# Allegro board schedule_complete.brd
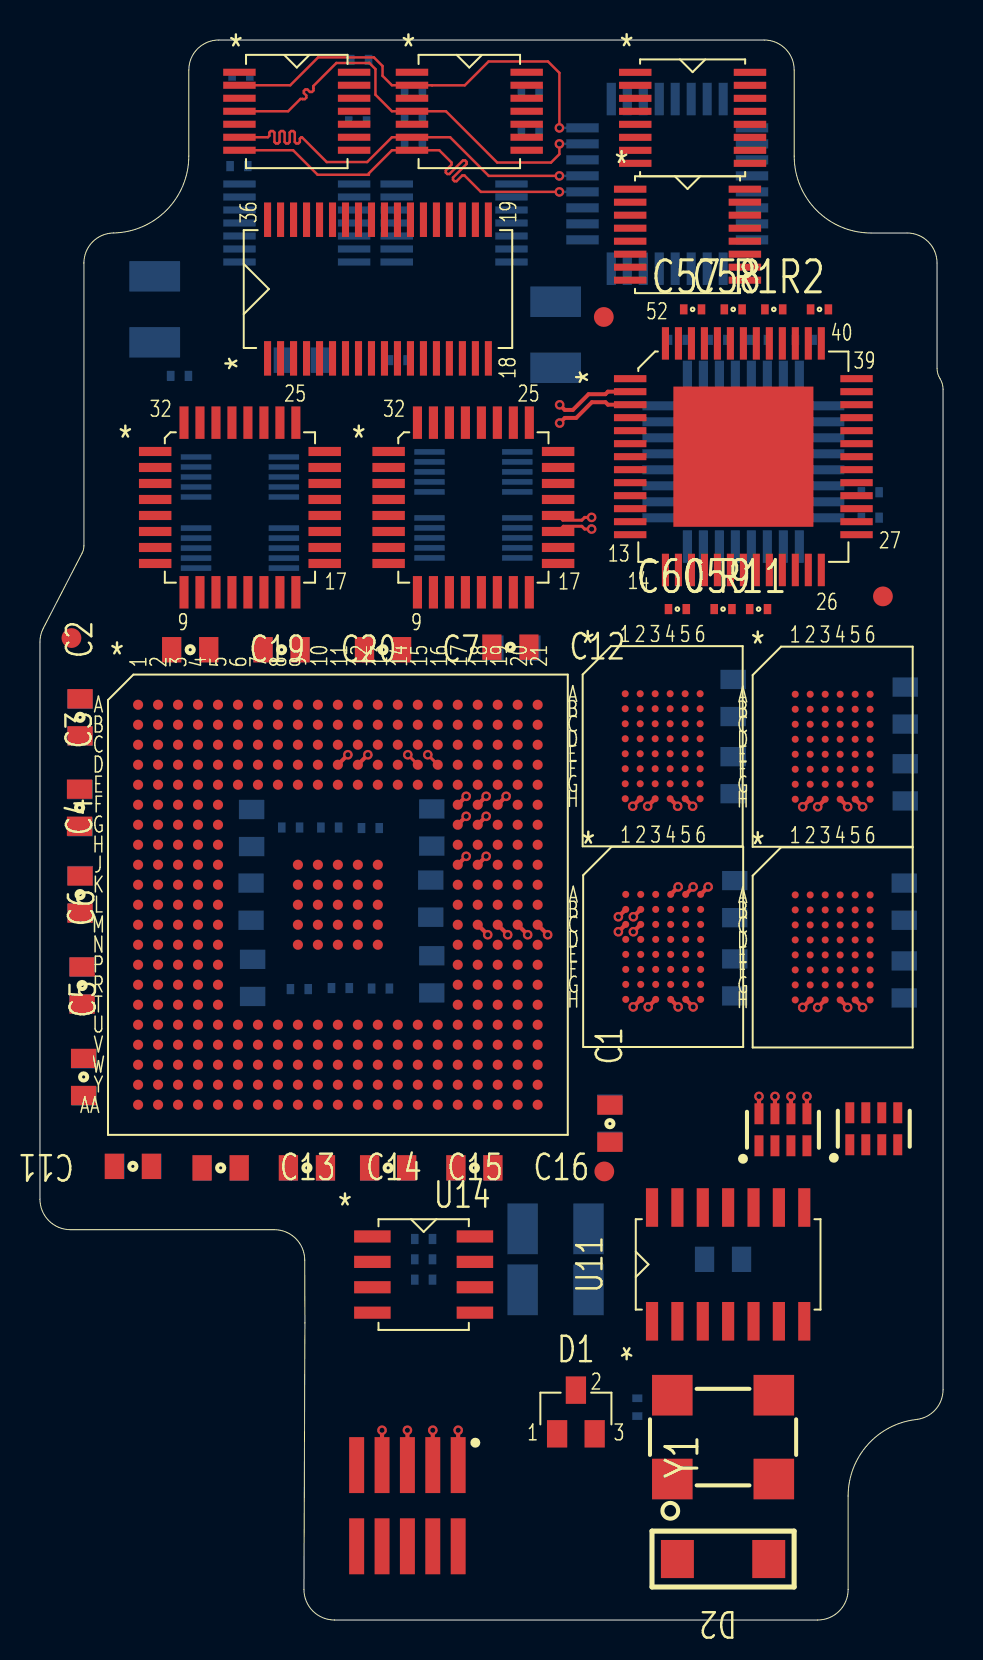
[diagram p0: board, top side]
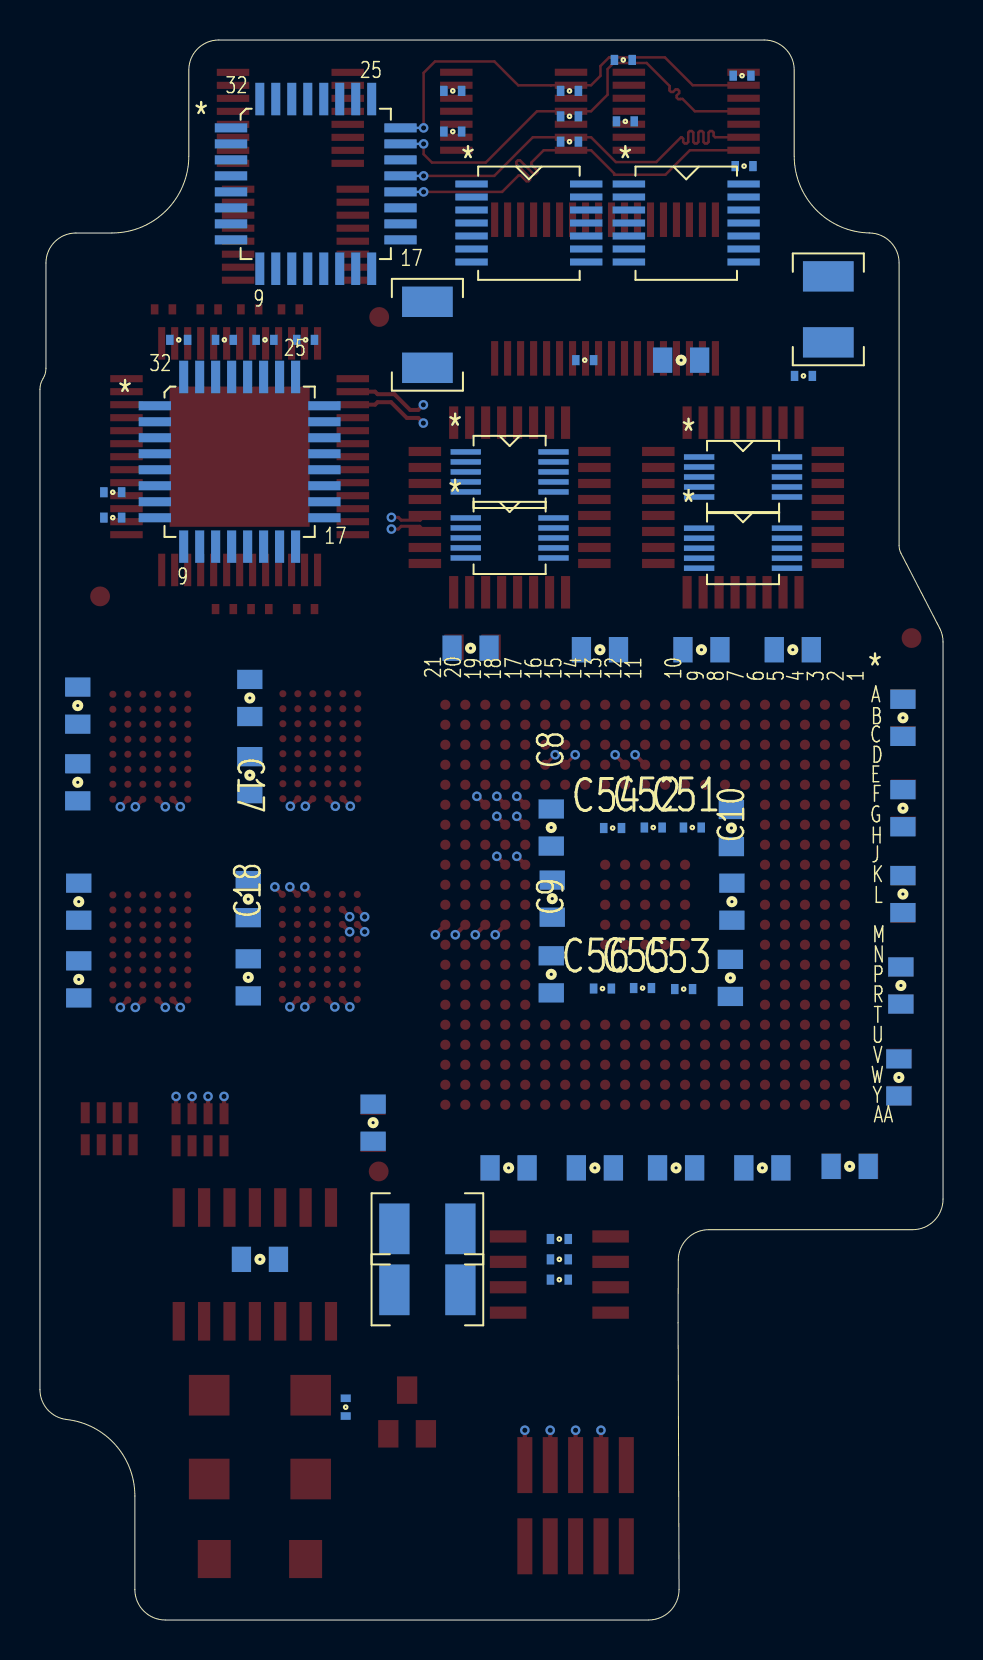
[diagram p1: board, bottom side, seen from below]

Outline 45.2 x 79 mm; copper layers: TOP, GND1, SIGNAL_1, PWR1, GND2, SIGNAL_2, PWR2, BOTTOM. Coordinates in mm from the lower left corner of the outline.
Outline path: 0,48.9 0,21.04 arc(0.45,19.96) 1.52,19.52 11.73,19.52 arc(12.8,19.07) 13.25,18 13.26,14.86 13.21,1.53 arc(13.66,0.45) 14.74,0 38.93,0 arc(40,0.45) 40.45,1.52 40.45,6.2 arc(41.43,8.77) 43.87,10.03 arc(44.82,10.52) 45.2,11.52 45.2,61.54 arc(45.16,61.81) 45.05,62.06 arc(44.94,62.32) 44.9,62.59 44.9,67.85 arc(44.46,68.91) 43.4,69.35 41.6,69.35 arc(38.88,70.48) 37.75,73.2 37.75,77.5 arc(37.31,78.56) 36.25,79 8.95,79 arc(7.89,78.56) 7.45,77.5 7.45,73.2 arc(6.35,70.5) 3.67,69.35 arc(2.63,68.9) 2.2,67.85 2.2,53.71 arc(2.18,53.52) 2.11,53.35 0.17,49.59 arc(0.04,49.26) 0,48.9

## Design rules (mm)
constraint set DEFAULT: min track width 0.127
net group CLOCK1: nets CLOCK1 CLOCK_OUT
net group DP: nets DP_N DP_P
net group PHASE: nets PHASE_N PHASE_P
net group BYTELANE0: nets DDR3_DM0 DDR3_DQ0 DDR3_DQ1 DDR3_DQ2 DDR3_DQ3 DDR3_DQS0_N DDR3_DQS0_P
net group LENGTH: nets LENGTH1 LENGTH2 LENGTH3 LENGTH4

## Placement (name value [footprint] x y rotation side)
C1  120PF  [SMC0805]  28.53 24.82 90 top
C2  120PF  [SMC0805]  2.01 45.14 90 top
C3  120PF  [SMC0805]  1.98 40.61 90 top
C4  120PF  [SMC0805]  2.01 36.27 90 top
C5  120PF  [SMC0805]  2.19 27.15 90 top
C6  120PF  [SMC0805]  2.11 31.72 90 top
C7  120PF  [SMC0805]  17.17 48.51 0 top
C8  120PF  [SMC0805]  19.61 39.62 90 bottom
C9  120PF  [SMC0805]  19.61 32.28 90 bottom
C10  120PF  [SMC0805]  10.57 35.92 90 bottom
C11  120PF  [SMC0805]  4.65 22.68 180 top
C12  120PF  [SMC0805]  23.55 48.64 0 top
C13  120PF  [SMC0805]  9.04 22.61 0 top
C14  120PF  [SMC0805]  13.36 22.61 0 top
C15  120PF  [SMC0805]  17.43 22.61 0 top
C16  120PF  [SMC0805]  21.74 22.61 0 top
C17  120PF  [SMC0805]  34.7 46.1 270 bottom
C18  120PF  [SMC0805]  34.77 32.13 90 bottom
C19  120PF  [SMC0805]  7.52 48.51 0 top
C20  120PF  [SMC0805]  12.09 48.51 0 top
C21  120PF  [SMC0805]  2.01 36.3 90 bottom
C22  120PF  [SMC0805]  2.11 31.72 90 bottom
C23  120PF  [SMC0805]  12.09 48.51 0 bottom
C24  120PF  [SMC0805]  2.21 27.13 90 bottom
C25  120PF  [SMC0805]  9.04 22.61 0 bottom
C26  120PF  [SMC0805]  17.17 48.51 0 bottom
C27  120PF  [SMC0805]  23.65 48.59 0 bottom
C28  120PF  [SMC0805]  19.56 36.07 90 bottom
C29  120PF  [SMC0805]  10.64 32.11 90 bottom
C30  120PF  [SMC0805]  10.59 39.6 90 bottom
C31  120PF  [SMC0805]  28.53 24.87 90 bottom
C32  120PF  [SMC0805]  7.52 48.51 0 bottom
C33  120PF  [SMC0805]  17.43 22.61 0 bottom
C34  120PF  [SMC0805]  13.36 22.61 0 bottom
C35  120PF  [SMC0805]  21.74 22.61 0 bottom
C36  120PF  [SMC0805]  4.68 22.68 180 bottom
C37  120PF  [SMC0805]  34.77 36.04 270 bottom
C38  120PF  [SMC0805]  34.7 42.24 270 bottom
C39  120PF  [SMC0805]  2.01 40.59 90 bottom
C40  120PF  [SMC0805]  2.01 45.11 90 bottom
C41  10uF  [1210RF]  5.74 65.53 270 bottom
C42  10uF  [1210RF]  25.81 64.26 270 bottom
C43  10uF  [1210RF]  25.81 16.51 180 bottom
C44  10uF  [1210RF]  25.81 19.56 180 bottom
C45  120PF  [SMC0805]  13.11 62.99 180 bottom
C46  120PF  [SMC0805]  43.26 32.03 90 bottom
C47  120PF  [SMC0805]  43.26 35.92 270 bottom
C48  120PF  [SMC0805]  43.31 45.72 270 bottom
C49  120PF  [SMC0805]  43.31 41.88 90 bottom
C50  120PF  [SMC0805]  34.19 18.03 180 bottom
C51  .1UF  [R_0402]  12.55 39.62 180 bottom
C52  .1UF  [R_0402]  14.5 39.62 180 bottom
C53  .1UF  [R_0402]  12.98 31.55 180 bottom
C54  .1UF  [R_0402]  16.54 39.6 180 bottom
C55  .1UF  [R_0402]  15.04 31.6 180 bottom
C56  .1UF  [R_0402]  17.04 31.57 180 bottom
C57  .1UF  [R_0402]  32.67 65.53 0 top
C58  .1UF  [R_0402]  34.7 65.53 0 top
C59  .1UF  [R_0402]  34.19 50.55 0 top
C60  .1UF  [R_0402]  31.9 50.55 0 top
D1  -  [SOT23_132]  26.82 10.41 0 top
D2  V  [SMF1806]  34.19 3.05 180 top
J1  FTSH-105-XX-X-DV  [SAMTEC_FTSH-105-XX-X-DV]  18.39 5.71 0 top
NOREF  -  [unnamed]  26.82 3.05 0 top
R1  10K  [R_0402]  36.73 65.53 0 top
R2  10K  [R_0402]  39.02 65.53 0 top
R3  10K  [R_0402]  31.9 64.01 180 bottom
R4  10K  [R_0402]  33.94 64.01 180 bottom
R5  10K  [R_0402]  35.97 64.01 180 bottom
R6  10K  [R_0402]  38.25 64.01 180 bottom
R7  10K  [R_0402]  17.93 62.99 180 bottom
R8  10K  [R_0402]  24.54 74.42 180 bottom
R9  10K  [R_0402]  16 78 180 bottom
R10  10K  [R_0402]  15.9 74.93 180 bottom
R11  10K  [R_0402]  35.97 50.55 0 top
R12  10K  [R_0402]  24.54 76.45 180 bottom
R13  10K  [R_0402]  18.7 76.45 180 bottom
R14  10K  [R_0402]  9.96 72.69 180 bottom
R15  10K  [R_0402]  10.06 77.22 180 bottom
R16  10K  [R_0402]  6.99 62.2 180 bottom
R17  10K  [R_0402]  18.7 75.18 180 bottom
R18  10K  [R_0402]  18.7 73.91 180 bottom
R19  10K  [R_0402]  41.56 56.39 180 bottom
R20  10K  [R_0402]  19.2 18.03 180 bottom
R21  10K  [R_0402]  19.2 19.05 180 bottom
R22  10K  [R_0402]  19.2 17.02 180 bottom
R23  10K  [R_0402]  41.56 55.12 180 bottom
R24  10K  [R_0402]  29.9 10.64 90 bottom
RN1  10K  [RESCAV80P160X320X70-8N]  37.19 24.51 90 top
RN2  10K  [RESCAV80P160X320X70-8N]  41.73 24.56 90 top
U1  -  [TSSOP14_26CC_BD4-4MM]  12.85 75.44 0 top
U2  -  [TSSOP14_26CC_BD4-4MM]  21.49 75.44 0 top
U3  -  [TSSOP14_26CC_BD4-4MM]  12.85 69.85 180 bottom
U4  -  [TSSOP14_26CC_BD4-4MM]  20.73 69.85 180 bottom
U5  -  [BGA345_BD23X23MM]  14.91 35.76 0 top
U7  -  [BGA48_BD7-5X9-5MM]  31.17 43.69 0 top
U8  -  [BGA48_BD7-5X9-5MM]  39.68 43.66 0 top
U9  -  [BGA48_BD7-5X9-5MM]  39.68 33.63 0 top
U10  -  [BGA48_BD7-5X9-5MM]  31.19 33.66 0 top
U11  -  [SO14NB]  34.44 17.78 90 top
U12  -  [TQFP52_BD10X10MM_THERM]  35.21 58.17 0 top
U13  -  [SSOP36_26CC_BD5-3MM]  16.92 66.55 90 top
U14  -  [SO8NB_V2]  19.2 17.27 0 top
U15  -  [TSSOP16_26CC_BD4-4MM]  32.41 69.27 0 top
U16  -  [TSSOP16_26CC_BD4-4MM]  32.67 75.11 0 top
U17  -  [TQFP32_32CC_BD7X7MM]  10.01 55.63 0 top
U18  -  [TQFP32_32CC_BD7X7MM]  21.69 55.63 0 top
U19  -  [TQFP32_32CC_BD7X7MM]  35.21 57.91 180 bottom
U20  -  [TQFP32_32CC_BD7X7MM]  31.4 71.81 180 bottom
U21  -  [MSOP10_20CC_BD3MM]  10.01 57.15 180 bottom
U22  -  [MSOP10_20CC_BD3MM]  10.01 53.59 180 bottom
U23  -  [MSOP10_20CC_BD3MM]  21.69 57.4 180 bottom
U24  -  [MSOP10_20CC_BD3MM]  21.69 54.1 180 bottom
Y1  -  [4CERAMIC]  34.19 9.14 90 top

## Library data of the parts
C1-C40 C45-C50 = CAP: Tolerance: 5%; alternate symbols: (VSMC0805L,VSMC0805R,VSMC0805B,SMC0805); part number: CAP_805-120PF,5%,50V,805; signal model: capacitor120pF; tolerance: 5%; signal model: DEFAULT_CAPACITOR_120.000000pF_2_1
C41-C44 = CAP: Tolerance: +80-20%; User Part Number: 110-1925-01; alternate symbols: (1210RF_WVI_10P;1210RF_V12P;1210WS;1210WS_WVI_10P); part number: CAP_SMT1210-110-1925-01,10UF,+80-20%,16V; tolerance: +80-20%; signal model: DEFAULT_CAPACITOR_1e+07pF_2_1
C51-C60 = CAP: alternate symbols: (VSMC0603L,VSMC0603R,VSMC0603B,SMC0603); part number: CAP_402-.1UF,&10%,80%,6.3V; signal model: capacitor0pF; tolerance: 10%; signal model: DEFAULT_CAPACITOR_100000pF_2_1
D1 = RCNET: User Part Number: 120-3831-01; Tolerance: 10%; part number: RCNET_SOT23-120-3831-01,CTXS03,50,46.4,50,150PF,10%; tolerance: 10%
D2 = BEAD_1806: Tolerance: T; User Part Number: P; part number: BEAD_1806_SMF1806-FBMH4516,TAIYO_FERRITE_BEAD,6A
J1 = SAMTEC_FTSH
R1-R24 = RES: alternate symbols: (VSMR0402B,VSMR0402R,VSMR0402L,0402); part number: RES_402-10K,1%,0402; signal model: resistor10K; tolerance: 1%; signal model: DEFAULT_RESISTOR_10000OHM_2_1
RN1 RN2 = RESNET_8: signal model: DEFAULT_RESISTOR_PACK_4_10000OHM
U1-U4 = LVC07: User Part Number: 100-7328-01; Tolerance: ***; part number: LVC07_TSSOP-100-7328-01,APW
U5 = TALON: User Part Number: 528-1123-01; Tolerance: ***; alternate symbols: (BGA345_BD23X23MM_NF); part number: TALON_BGA345-528-1123-01
U7-U10 = SRAM1MX16: User Part Number: 102-0026-01; Tolerance: ***; part number: SRAM1MX16_BGA-102-0026-01,55NS,K6F1616U6A-EF55
U11 = LVC00: User Part Number: 100-4554-01; Tolerance: ***; part number: LVC00_SO-100-4554-01
U12 = MC100ES6220: Tolerance: ***; User Part Number: 103-0009-01; alternate symbols: (TQFP52_BD10X10MM_THERM_NF); part number: MC100ES6220_TQFP-103-0009-01
U13 = LTC3731: User Part Number: 104-0019-01; Tolerance: ***; part number: LTC3731_SSOP36-104-0019-01
U14 = EEPROM8KX8: Tolerance: ***; User Part Number: 101-0054-01; part number: EEPROM8KX8_SO8-101-0054-01,M34D64
U15 U16 = PCA9554: User Part Number: 100-7579-01; Tolerance: ***; part number: PCA9554_TSSOP-100-7579-01
U17-U20 = CY2HH8110: Tolerance: ***; User Part Number: 100-7829-01; part number: CY2HH8110_TQFP-100-7829-01
U21-U24 = MAX1343: User Part Number: 104-0099-01; Tolerance: ***; part number: MAX1343_MSOP-104-0099-01,10BITADC
Y1 = OSC: part number: OSC_CERAMIC-66.00MHZ,CLOCKING,SG8002JF

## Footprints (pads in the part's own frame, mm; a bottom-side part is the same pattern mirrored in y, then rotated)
4CERAMIC
  rect 2.032x2.032 smd: 1(-2.095,2.54) 2(-2.095,-2.54) 3(2.095,-2.54) 4(2.095,2.54)
1210RF
  rect 1.524x2.54 smd: 1(-1.651,0) 2(1.651,0)
BGA48_BD7-5X9-5MM
  round 0.356 smd: A1(-1.875,2.625) A2(-1.125,2.625) A3(-0.375,2.625) A4(0.375,2.625) A5(1.125,2.625) A6(1.875,2.625) B1(-1.875,1.875) B2(-1.125,1.875) B3(-0.375,1.875) B4(0.375,1.875) B5(1.125,1.875) B6(1.875,1.875) C1(-1.875,1.125) C2(-1.125,1.125) C3(-0.375,1.125) C4(0.375,1.125) C5(1.125,1.125) C6(1.875,1.125) D1(-1.875,0.375) D2(-1.125,0.375) D3(-0.375,0.375) D4(0.375,0.375) D5(1.125,0.375) D6(1.875,0.375) E1(-1.875,-0.375) E2(-1.125,-0.375) E3(-0.375,-0.375) E4(0.375,-0.375) E5(1.125,-0.375) E6(1.875,-0.375) F1(-1.875,-1.125) F2(-1.125,-1.125) F3(-0.375,-1.125) F4(0.375,-1.125) F5(1.125,-1.125) F6(1.875,-1.125) G1(-1.875,-1.875) G2(-1.125,-1.875) G3(-0.375,-1.875) G4(0.375,-1.875) G5(1.125,-1.875) G6(1.875,-1.875) H1(-1.875,-2.625) H2(-1.125,-2.625) H3(-0.375,-2.625) H4(0.375,-2.625) H5(1.125,-2.625) H6(1.875,-2.625)
BGA345_BD23X23MM
  round 0.991 smd: (-13.335,13.335) (13.335,-13.335)
  round 0.508 smd: A1(-10,10) A2(-9,10) A3(-8,10) A4(-7,10) A5(-6,10) A6(-5,10) A7(-4,10) A8(-3,10) A9(-2,10) A10(-1,10) A11(0,10) A12(1,10) A13(2,10) A14(3,10) A15(4,10) A16(5,10) A17(6,10) A18(7,10) A19(8,10) A20(9,10) A21(10,10) AA1(-10,-10) AA2(-9,-10) AA3(-8,-10) AA4(-7,-10) AA5(-6,-10) AA6(-5,-10) AA7(-4,-10) AA8(-3,-10) AA9(-2,-10) AA10(-1,-10) AA11(0,-10) AA12(1,-10) AA13(2,-10) AA14(3,-10) AA15(4,-10) AA16(5,-10) AA17(6,-10) AA18(7,-10) AA19(8,-10) AA20(9,-10) AA21(10,-10) B1(-10,9) B2(-9,9) B3(-8,9) B4(-7,9) B5(-6,9) B6(-5,9) B7(-4,9) B8(-3,9) B9(-2,9) B10(-1,9) B11(0,9) B12(1,9) B13(2,9) B14(3,9) B15(4,9) B16(5,9) B17(6,9) B18(7,9) B19(8,9) B20(9,9) B21(10,9) C1(-10,8) C2(-9,8) C3(-8,8) C4(-7,8) C5(-6,8) C6(-5,8) C7(-4,8) C8(-3,8) C9(-2,8) C10(-1,8) C11(0,8) C12(1,8) C13(2,8) C14(3,8) C15(4,8) C16(5,8) C17(6,8) C18(7,8) C19(8,8) C20(9,8) C21(10,8) D1(-10,7) D2(-9,7) D3(-8,7) D4(-7,7) D5(-6,7) D6(-5,7) D7(-4,7) D8(-3,7) D9(-2,7) D10(-1,7) D11(0,7) D12(1,7) D13(2,7) D14(3,7) D15(4,7) D16(5,7) D17(6,7) D18(7,7) D19(8,7) D20(9,7) D21(10,7) E1(-10,6) E2(-9,6) E3(-8,6) E4(-7,6) E5(-6,6) E6(-5,6) E7(-4,6) E8(-3,6) E9(-2,6) E10(-1,6) E11(0,6) E12(1,6) E13(2,6) E14(3,6) E15(4,6) E16(5,6) E17(6,6) E18(7,6) E19(8,6) E20(9,6) E21(10,6) F1(-10,5) F2(-9,5) F3(-8,5) F4(-7,5) F5(-6,5) F17(6,5) F18(7,5) F19(8,5) F20(9,5) F21(10,5) G1(-10,4) G2(-9,4) G3(-8,4) G4(-7,4) G5(-6,4) G17(6,4) G18(7,4) G19(8,4) G20(9,4) G21(10,4) H1(-10,3) H2(-9,3) H3(-8,3) H4(-7,3) H5(-6,3) H17(6,3) H18(7,3) H19(8,3) H20(9,3) H21(10,3) J1(-10,2) J2(-9,2) J3(-8,2) J4(-7,2) J5(-6,2) J9(-2,2) J10(-1,2) J11(0,2) J12(1,2) J13(2,2) J17(6,2) J18(7,2) J19(8,2) J20(9,2) J21(10,2) K1(-10,1) K2(-9,1) K3(-8,1) K4(-7,1) K5(-6,1) K9(-2,1) K10(-1,1) K11(0,1) K12(1,1) K13(2,1) K17(6,1) K18(7,1) K19(8,1) K20(9,1) K21(10,1) L1(-10,0) L2(-9,0) L3(-8,0) L4(-7,0) L5(-6,0) L9(-2,0) L10(-1,0) L11(0,0) L12(1,0) L13(2,0) L17(6,0) L18(7,0) L19(8,0) L20(9,0) L21(10,0) M1(-10,-1) M2(-9,-1) M3(-8,-1) M4(-7,-1) M5(-6,-1) M9(-2,-1) M10(-1,-1) M11(0,-1) M12(1,-1) M13(2,-1) M17(6,-1) M18(7,-1) M19(8,-1) M20(9,-1) M21(10,-1) N1(-10,-2) N2(-9,-2) N3(-8,-2) N4(-7,-2) N5(-6,-2) N9(-2,-2) N10(-1,-2) N11(0,-2) N12(1,-2) N13(2,-2) N17(6,-2) N18(7,-2) N19(8,-2) N20(9,-2) N21(10,-2) P1(-10,-3) P2(-9,-3) P3(-8,-3) P4(-7,-3) P5(-6,-3) P17(6,-3) P18(7,-3) P19(8,-3) P20(9,-3) P21(10,-3) R1(-10,-4) R2(-9,-4) R3(-8,-4) R4(-7,-4) R5(-6,-4) R17(6,-4) R18(7,-4) R19(8,-4) R20(9,-4) R21(10,-4) T1(-10,-5) T2(-9,-5) T3(-8,-5) T4(-7,-5) T5(-6,-5) T17(6,-5) T18(7,-5) T19(8,-5) T20(9,-5) T21(10,-5) U1(-10,-6) U2(-9,-6) U3(-8,-6) U4(-7,-6) U5(-6,-6) U6(-5,-6) U7(-4,-6) U8(-3,-6) U9(-2,-6) U10(-1,-6) U11(0,-6) U12(1,-6) U13(2,-6) U14(3,-6) U15(4,-6) U16(5,-6) U17(6,-6) U18(7,-6) U19(8,-6) U20(9,-6) U21(10,-6) V1(-10,-7) V2(-9,-7) V3(-8,-7) V4(-7,-7) V5(-6,-7) V6(-5,-7) V7(-4,-7) V8(-3,-7) V9(-2,-7) V10(-1,-7) V11(0,-7) V12(1,-7) V13(2,-7) V14(3,-7) V15(4,-7) V16(5,-7) V17(6,-7) V18(7,-7) V19(8,-7) V20(9,-7) V21(10,-7) W1(-10,-8) W2(-9,-8) W3(-8,-8) W4(-7,-8) W5(-6,-8) W6(-5,-8) W7(-4,-8) W8(-3,-8) W9(-2,-8) W10(-1,-8) W11(0,-8) W12(1,-8) W13(2,-8) W14(3,-8) W15(4,-8) W16(5,-8) W17(6,-8) W18(7,-8) W19(8,-8) W20(9,-8) W21(10,-8) Y1(-10,-9) Y2(-9,-9) Y3(-8,-9) Y4(-7,-9) Y5(-6,-9) Y6(-5,-9) Y7(-4,-9) Y8(-3,-9) Y9(-2,-9) Y10(-1,-9) Y11(0,-9) Y12(1,-9) Y13(2,-9) Y14(3,-9) Y15(4,-9) Y16(5,-9) Y17(6,-9) Y18(7,-9) Y19(8,-9) Y20(9,-9) Y21(10,-9)
MSOP10_20CC_BD3MM
  rect 1.524x0.279 smd: 1(-2.197,1) 2(-2.197,0.5) 3(-2.197,0) 4(-2.197,-0.5) 5(-2.197,-1) 6(2.197,-1) 7(2.197,-0.5) 8(2.197,0) 9(2.197,0.5) 10(2.197,1)
R_0402
  rect 0.381x0.508 smd: 1(-0.445,0) 2(0.445,0)
RESCAV80P160X320X70-8N
  rect 1.05x0.45 smd: 1(-0.8,1.2) 2(-0.8,0.4) 3(-0.8,-0.4) 4(-0.8,-1.2) 5(0.8,-1.2) 6(0.8,-0.4) 7(0.8,0.4) 8(0.8,1.2)
SAMTEC_FTSH-105-XX-X-DV
  rect 0.75x2.8 smd: 1(2.54,2.03) 2(2.54,-2.03) 3(1.27,2.03) 4(1.27,-2.03) 5(0,2.03) 6(0,-2.03) 7(-1.27,2.03) 8(-1.27,-2.03) 9(-2.54,2.03) 10(-2.54,-2.03)
SMC0805
  rect 0.965x1.27 smd: 1(-0.927,0) 2(0.927,0)
SMF1806
  rect 1.651x1.905 smd: 1(-2.286,0) 2(2.286,0)
SO8NB_V2
  rect 1.829x0.61 smd: 1(-2.565,1.905) 2(-2.565,0.635) 3(-2.565,-0.635) 4(-2.565,-1.905) 5(2.565,-1.905) 6(2.565,-0.635) 7(2.565,0.635) 8(2.565,1.905)
SO14NB
  rect 1.93x0.61 smd: 1(-2.845,3.81) 2(-2.845,2.54) 3(-2.845,1.27) 4(-2.845,0) 5(-2.845,-1.27) 6(-2.845,-2.54) 7(-2.845,-3.81) 8(2.845,-3.81) 9(2.845,-2.54) 10(2.845,-1.27) 11(2.845,0) 12(2.845,1.27) 13(2.845,2.54) 14(2.845,3.81)
SOT23_132
  rect 1.016x1.372 smd: 1(-0.94,-1.105) 2(0,1.079) 3(0.94,-1.105)
SSOP36_26CC_BD5-3MM
  rect 1.727x0.356 smd: 1(-3.467,5.525) 2(-3.467,4.875) 3(-3.467,4.225) 4(-3.467,3.575) 5(-3.467,2.925) 6(-3.467,2.275) 7(-3.467,1.625) 8(-3.467,0.975) 9(-3.467,0.325) 10(-3.467,-0.325) 11(-3.467,-0.975) 12(-3.467,-1.625) 13(-3.467,-2.275) 14(-3.467,-2.925) 15(-3.467,-3.575) 16(-3.467,-4.225) 17(-3.467,-4.875) 18(-3.467,-5.525) 19(3.467,-5.525) 20(3.467,-4.875) 21(3.467,-4.225) 22(3.467,-3.575) 23(3.467,-2.925) 24(3.467,-2.275) 25(3.467,-1.625) 26(3.467,-0.975) 27(3.467,-0.325) 28(3.467,0.325) 29(3.467,0.975) 30(3.467,1.625) 31(3.467,2.275) 32(3.467,2.925) 33(3.467,3.575) 34(3.467,4.225) 35(3.467,4.875) 36(3.467,5.525)
TQFP32_32CC_BD7X7MM
  rect 1.626x0.457 smd: 1(-4.242,2.8) 2(-4.242,2) 3(-4.242,1.2) 4(-4.242,0.4) 5(-4.242,-0.4) 6(-4.242,-1.2) 7(-4.242,-2) 8(-4.242,-2.8) 17(4.242,-2.8) 18(4.242,-2) 19(4.242,-1.2) 20(4.242,-0.4) 21(4.242,0.4) 22(4.242,1.2) 23(4.242,2) 24(4.242,2.8)
  rect 0.457x1.626 smd: 9(-2.8,-4.242) 10(-2,-4.242) 11(-1.2,-4.242) 12(-0.4,-4.242) 13(0.4,-4.242) 14(1.2,-4.242) 15(2,-4.242) 16(2.8,-4.242) 25(2.8,4.242) 26(2,4.242) 27(1.2,4.242) 28(0.4,4.242) 29(-0.4,4.242) 30(-1.2,4.242) 31(-2,4.242) 32(-2.8,4.242)
TQFP52_BD10X10MM_THERM
  round 0.991 smd: (-6.985,6.985) (6.985,-6.985)
  rect 1.626x0.356 smd: 1(-5.664,3.9) 2(-5.664,3.25) 3(-5.664,2.6) 4(-5.664,1.95) 5(-5.664,1.3) 6(-5.664,0.65) 7(-5.664,0) 8(-5.664,-0.65) 9(-5.664,-1.3) 10(-5.664,-1.95) 11(-5.664,-2.6) 12(-5.664,-3.25) 13(-5.664,-3.9) 27(5.664,-3.9) 28(5.664,-3.25) 29(5.664,-2.6) 30(5.664,-1.95) 31(5.664,-1.3) 32(5.664,-0.65) 33(5.664,0) 34(5.664,0.65) 35(5.664,1.3) 36(5.664,1.95) 37(5.664,2.6) 38(5.664,3.25) 39(5.664,3.9)
  rect 0.356x1.626 smd: 14(-3.9,-5.664) 15(-3.25,-5.664) 16(-2.6,-5.664) 17(-1.95,-5.664) 18(-1.3,-5.664) 19(-0.65,-5.664) 20(0,-5.664) 21(0.65,-5.664) 22(1.3,-5.664) 23(1.95,-5.664) 24(2.6,-5.664) 25(3.25,-5.664) 26(3.9,-5.664) 40(3.9,5.664) 41(3.25,5.664) 42(2.6,5.664) 43(1.95,5.664) 44(1.3,5.664) 45(0.65,5.664) 46(0,5.664) 47(-0.65,5.664) 48(-1.3,5.664) 49(-1.95,5.664) 50(-2.6,5.664) 51(-3.25,5.664) 52(-3.9,5.664)
TSSOP14_26CC_BD4-4MM
  rect 1.626x0.356 smd: 1(-2.87,1.95) 2(-2.87,1.3) 3(-2.87,0.65) 4(-2.87,0) 5(-2.87,-0.65) 6(-2.87,-1.3) 7(-2.87,-1.95) 8(2.87,-1.95) 9(2.87,-1.3) 10(2.87,-0.65) 11(2.87,0) 12(2.87,0.65) 13(2.87,1.3) 14(2.87,1.95)
TSSOP16_26CC_BD4-4MM
  rect 1.626x0.356 smd: 1(-2.87,2.275) 2(-2.87,1.625) 3(-2.87,0.975) 4(-2.87,0.325) 5(-2.87,-0.325) 6(-2.87,-0.975) 7(-2.87,-1.625) 8(-2.87,-2.275) 9(2.87,-2.275) 10(2.87,-1.625) 11(2.87,-0.975) 12(2.87,-0.325) 13(2.87,0.325) 14(2.87,0.975) 15(2.87,1.625) 16(2.87,2.275)
unnamed
  round 0 hole 3.175 unplated: (0,0)

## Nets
GND: C1.2(B<0>) C2.2(B<0>) C3.2(B<0>) C4.2(B<0>) C5.2(B<0>) C6.2(B<0>) C7.2(B<0>) C8.2(B<0>) C9.2(B<0>) C10.2(B<0>) C11.2(B<0>) C12.2(B<0>) C13.2(B<0>) C14.2(B<0>) C15.2(B<0>) C16.2(B<0>) C17.2(B<0>) C18.2(B<0>) C19.2(B<0>) C20.2(B<0>) C21.2(B<0>) C22.2(B<0>) C23.2(B<0>) C24.2(B<0>) C25.2(B<0>) C26.2(B<0>) C27.2(B<0>) C28.2(B<0>) C29.2(B<0>) C30.2(B<0>) C31.2(B<0>) C32.2(B<0>) C33.2(B<0>) C34.2(B<0>) C35.2(B<0>) C36.2(B<0>) C37.2(B<0>) C38.2(B<0>) C39.2(B<0>) C40.2(B<0>) C41.2(B<0>) C42.2(B<0>) C43.1 C44.1 C45.2(B<0>) C46.2(B<0>) C47.2(B<0>) C48.2(B<0>) C49.2(B<0>) C50.2(B<0>) C51.2(B<0>) C52.2(B<0>) C53.2(B<0>) C54.2(B<0>) C55.2(B<0>) C56.2(B<0>) C57.2(B<0>) C58.2(B<0>) C59.2(B<0>) C60.2(B<0>) U2.1 U3.1 U4.1 U7.D3 U7.D4 U7.F3 U7.F4 U8.D3 U8.D4 U8.F3 U8.F4 U9.D3 U9.D4 U9.F3 U9.F4 U10.D3 U10.D4 U10.F3 U10.F4 U11.7 U12.7 U12.13 U12.20 U12.26 U12.29 U12.36 U12.45 U12.52 U13.7 U13.15 U13.22 U13.34 U14.1 U14.7(WC_N) U15.1 U16.1 U17.4 U17.13 U17.21 U17.28 U18.4 U18.13 U18.21 U18.29(VDD<8>) U19.3 U19.14 U19.18 U19.22 U19.28 U20.4 U20.13 U20.18 U20.29(VDD<8>) U21.1 U22.1 U23.1 U24.1
VCC: C1.1 C2.1 C3.1 C4.1 C5.1 C6.1 C7.1 C8.1 C9.1 C10.1 C11.1 C12.1 C13.1 C14.1 C15.1 C16.1 C17.1 C18.1 C19.1 C20.1 C21.1 C22.1 C23.1 C24.1 C25.1 C26.1 C27.1 C28.1 C29.1 C30.1 C31.1 C32.1 C33.1 C34.1 C35.1 C36.1 C37.1 C38.1 C39.1 C40.1 C41.1 C42.1 C43.2(B<0>) C44.2(B<0>) C45.1 C46.1 C47.1 C48.1 C49.1 C50.1 C51.1 C52.1 C53.1 C54.1 C55.1 C56.1 C57.1 C58.1 C59.1 C60.1 D2.1 R22.2(B<0>) R23.2(B<0>) RN1.1 RN1.2 RN1.3 RN1.4 RN2.1 RN2.2 RN2.3 RN2.4 U1.5 U1.8 U2.5 U2.8 U3.8 U4.8 U7.C3 U7.C4 U7.E3 U7.E4 U8.C3 U8.C4 U8.E3 U8.E4 U9.C3 U9.C4 U9.E3 U9.E4 U10.C3 U10.C4 U10.E3 U10.E4 U11.14 U12.6 U12.12 U12.19 U12.25 U12.28 U12.37 U13.5 U13.18 U13.27 U13.36 U15.9 U15.14 U16.9 U16.13 U17.5 U17.19 U17.27 U18.14 U18.27 U20.5 U20.12 U20.19 U20.30 U21.9 U21.10(VDD) U22.9 U22.10(VDD) U23.9 U23.10(VDD) U24.9 U24.10(VDD) Y1.2 Y1.4(VCC)
1: U5.A1 U17.9
2: U5.A2 U17.10
3: U5.B2 U17.12
4: U5.B3 U17.14
5: U5.B4 U17.15
6: U5.C4 U17.16 U18.10
A6: U12.21
ANY_LAYER_NET: U3.13 U4.13 U13.35 U15.4
CLK_OUT: Y1.3
CLOCK1: R24.1 Y1.1
CLOCK_OUT: R24.2(B<0>) U11.1 U14.6
DDR3_A0: J1.1(TP-1) RN1.8 U5.M21 U7.H2 U8.H2 U9.H2 U10.H2
DDR3_A1: J1.3 RN1.7 U5.M20 U7.H3 U8.H3 U9.H3 U10.H3
DDR3_A2: J1.5 RN1.6 U5.M19 U7.H4 U8.H4 U9.H4 U10.H4
DDR3_A3: J1.7 RN1.5(B) U5.M18 U7.H5 U8.H5 U9.H5 U10.H5
DDR3_A4: J1.9 RN2.5(B) U5.M17 U7.F6 U8.F6 U9.F6 U10.F6
DDR3_A5: J1.10 RN2.6 U5.N21 U7.G6 U8.G6 U9.G6 U10.G6
DDR3_A6: J1.8 RN2.7 U5.P17 U7.G5(WE_N) U8.G5(WE_N) U9.G5(WE_N) U10.G5(WE_N)
DDR3_A7: J1.6 RN2.8 U5.N19 U7.G4 U8.G4 U9.G4 U10.G4
DDR3_DM0: U5.F19 U10.A4
DDR3_DQ0: U5.J17 U10.C2
DDR3_DQ1: U5.F18 U10.A5
DDR3_DQ2: U5.J18 U10.C1
DDR3_DQ3: U5.F17 U10.A6
DDR3_DQS0_N: U5.G17 U10.B1
DDR3_DQS0_P: U5.G18 U10.B2
DP_N: U5.D15 U18.19
DP_P: U5.D16 U18.20
HDI_STACK: U3.9 U4.2(Y<1>) U13.32 U15.3 U20.6
LENGTH1: U1.2(Y<1>) U2.2(Y<1>) U20.24
LENGTH2: U1.4 U2.4 U20.23
LENGTH3: U1.6 U2.6 U20.21
LENGTH4: U1.7 U2.7 U20.20
NET1: U1.9
NET2: U1.10 U4.12
NET3: U1.11 U4.11
NET4: U12.9(VEE2) U17.6 U18.6
NET5: D1.2 D2.2(B) U11.2 U14.2
NET7: D1.1 U14.3
NET8: R16.2(B<0>) U2.9 U12.11 U15.2 U17.30 U18.9 U19.27 U20.22
NET9: U12.8 U15.10 U17.2 U18.1
NET11: U2.13 U16.15
NET12: R14.2(B<0>) U3.12 U4.3 U4.9 U20.2
NET13: U12.34 U17.23 U18.23
NET14: U19.8 U21.4 U22.6 U23.4
NET15: U19.17 U22.8 U24.7
NET17: U13.9 U17.11
NET20: U13.10 U17.32
NET24: U3.7 U11.3(Y_N<0>) U11.4 U16.14 U17.18 U20.17
NET25: U3.2(Y<1>) U11.11 U17.29(VDD<8>)
NET28: U11.6 U14.5 U18.31
NET31: R13.1 U1.3 U1.14 U2.3
NET33: R11.2(B<0>) U14.4 U19.12
NET34: U16.10
PECL1_N: U3.11 U11.10 U17.3
PECL1_P: U1.12 U3.10 U11.9 U17.26
PECL2_N: U11.13 U17.17
PECL2_P: U11.12 U18.16 U20.15
PHASE_N: U5.D12 U12.3
PHASE_P: U5.D11 U12.2

Pads without a net: D1 3; J1 2 4; R1 1 2; R2 1 2; R3 1 2; R4 1 2; R5 1 2; R6 1 2; R7 1 2; R8 1 2; R9 1 2; R10 1 2; R11 1; R12 1 2; R13 2; R14 1; R15 1 2; R16 1; R17 1 2; R18 1 2; R19 1 2; R20 1 2; R21 1 2; R22 1; R23 1; U1 1 13; U2 10 11 12 14; U3 3 4 5 6 14; U4 4 5 6 7 10 14; U5 A3 A4 A5 A6 A7 A8 A9 A10 A11 A12 A13 A14 A15 A16 A17 A18 A19 A20 A21 AA1 AA2 AA3 AA4 AA5 AA6 AA7 AA8 AA9 AA10 AA11 AA12 AA13 AA14 AA15 AA16 AA17 AA18 AA19 AA20 AA21 B1 B5 B6 B7 B8 B9 B10 B11 B12 B13 B14 B15 B16 B17 B18 B19 B20 B21 C1 C2 C3 C5 C6 C7 C8 C9 C10 C11 C12 C13 C14 C15 C16 C17 C18 C19 C20 C21 D1 D2 D3 D4 D5 D6 D7 D8 D9 D10 D13 D14 D17 D18 D19 D20 D21 E1 E2 E3 E4 E5 E6 E7 E8 E9 E10 E11 E12 E13 E14 E15 E16 E17 E18 E19 E20 E21 F1 F2 F3 F4 F5 F20 F21 G1 G2 G3 G4 G5 G19 G20 G21 H1 H2 H3 H4 H5 H17 H18 H19 H20 H21 J1 J2 J3 J4 J5 J9 J10 J11 J12 J13 J19 J20 J21 K1 K2 K3 K4 K5 K9 K10 K11 K12 K13 K17 K18 K19 K20 K21 L1 L2 L3 L4 L5 L9 L10 L11 L12 L13 L17 L18 L19 L20 L21 M1 M2 M3 M4 M5 M9 M10 M11 M12 M13 N1 N2 N3 N4 N5 N9 N10 N11 N12 N13 N17 N18 N20 P1 P2 P3 P4 P5 P18 P19 P20 P21 R1 R2 R3 R4 R5 R17 R18 R19 R20 R21 T1 T2 T3 T4 T5 T17 T18 T19 T20 T21 U1 U2 U3 U4 U5 U6 U7 U8 U9 U10 U11 U12 U13 U14 U15 U16 U17 U18 U19 U20 U21 V1 V2 V3 V4 V5 V6 V7 V8 V9 V10 V11 V12 V13 V14 V15 V16 V17 V18 V19 V20 V21 W1 W2 W3 W4 W5 W6 W7 W8 W9 W10 W11 W12 W13 W14 W15 W16 W17 W18 W19 W20 W21 Y1 Y2 Y3 Y4 Y5 Y6 Y7 Y8 Y9 Y10 Y11 Y12 Y13 Y14 Y15 Y16 Y17 Y18 Y19 Y20 Y21; U7 A1 A2 A3 A4 A5 A6 B1 B2 B3 B4 B5 B6 C1 C2 C5 C6 D1 D2 D5 D6 E1 E2 E5 E6 F1 F2 F5 G1 G2 G3 H1 H6; U8 A1 A2 A3 A4 A5 A6 B1 B2 B3 B4 B5 B6 C1 C2 C5 C6 D1 D2 D5 D6 E1 E2 E5 E6 F1 F2 F5 G1 G2 G3 H1 H6; U9 A1 A2 A3 A4 A5 A6 B1 B2 B3 B4 B5 B6 C1 C2 C5 C6 D1 D2 D5 D6 E1 E2 E5 E6 F1 F2 F5 G1 G2 G3 H1 H6; U10 A1 A2 A3 B3 B4 B5 B6 C5 C6 D1 D2 D5 D6 E1 E2 E5 E6 F1 F2 F5 G1 G2 G3 H1 H6; U11 5 8; U12 1 4 5 10 14 15 16 17 18 22 23 24 27 30 31 32 33 35 38 39 40 41 42 43 44 46 47 48 49 50 51; U13 1 2 3 4 6 8 11 12 13 14 16 17 19 20 21 23 24 25 26 28 29 30 31 33; U14 8; U15 5 6 7 8 11 12 13 15 16; U16 2 3 4 5 6 7 8 11 12 16; U17 1 7 8 20 22 24 25 31; U18 2 3 5 7 8 11 12 15 17 18 22 24 25 26 28 30 32; U19 1 2 4 5 6 7 9 10 11 13 15 16 19 20 21 23 24 25 26 29 30 31 32; U20 1 3 7 8 9 10 11 14 16 25 26 27 28 31 32; U21 2 3 5 6 7 8; U22 2 3 4 5 7; U23 2 3 5 6 7 8; U24 2 3 4 5 6 8

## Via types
v1: diameter 0.483, hole 0.254, TOP to BOTTOM, 54 vias

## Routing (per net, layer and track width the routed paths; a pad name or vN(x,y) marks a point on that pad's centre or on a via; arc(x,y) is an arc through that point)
DDR3_A0: length 94.7
  TOP w0.209: U10.H2 v1(29.69,30.66) ; U5.M21 v1(25.41,34.26) ; RN1.8 v1(35.99,26.18) ; U8.H2 v1(38.18,40.66) ; U9.H2 v1(38.18,30.63) ; J1.1 v1(20.93,9.49) ; U7.H2 v1(29.67,40.69)
  SIGNAL_1 w0.146: v1(20.93,9.49) 25.41,13.97 v1(25.41,34.26) 23.4,36.27 21.01,36.27 19.97,37.31 19.97,41.1 20.85,41.99 28.37,41.99 v1(29.67,40.69) 30.66,39.7 35.05,39.7 36.02,40.66 v1(38.18,40.66) 38.18,37.41 37.67,37.41 37.67,37.13 38.68,37.13 38.68,36.86 37.67,36.86 37.67,36.59 38.68,36.59 38.68,36.31 38.18,36.31 v1(38.18,30.63) 35.08,30.63 34.15,31.57 30.6,31.57 v1(29.69,30.66)
  SIGNAL_2 w0.146: v1(35.99,26.18) 35.29,26.87 32.18,26.87 29.69,29.36 v1(29.69,30.66)
DDR3_A1: length 94.8
  TOP w0.209: U7.H3 v1(30.42,40.69) ; U9.H3 v1(38.93,30.63) ; RN1.7 v1(36.79,26.18) ; J1.3 v1(19.66,9.49) ; U8.H3 v1(38.93,40.66) ; U5.M20 v1(24.41,34.26) ; U10.H3 v1(30.44,30.66)
  SIGNAL_1 w0.146: v1(19.66,9.49) 24.41,14.24 v1(24.41,34.26) 22.91,35.76 20.98,35.76 19.69,37.06 19.69,41.33 20.63,42.27 28.84,42.27 v1(30.42,40.69) 31.16,39.95 34.87,39.95 36,41.08 38.51,41.08 v1(38.93,40.66) 38.93,34.39 39.43,34.39 39.43,34.11 38.42,34.11 38.42,33.84 39.43,33.84 39.43,33.57 38.93,33.57 v1(38.93,30.63) 38.51,30.21 35.02,30.21 33.91,31.32 31.11,31.32 v1(30.44,30.66)
  SIGNAL_2 w0.146: v1(36.79,26.18) 35.56,27.41 32.72,27.41 30.44,29.68 v1(30.44,30.66)
DDR3_A2: length 94.4
  TOP w0.209: RN1.6 v1(37.59,26.18) ; U10.H4 v1(31.94,30.66) ; U9.H4 v1(40.43,30.63) ; U5.M19 v1(23.41,34.26) ; U8.H4 v1(40.43,40.66) ; U7.H4 v1(31.92,40.69) ; J1.5 v1(18.39,9.49)
  SIGNAL_1 w0.146: v1(18.39,9.49) 23.41,14.51 v1(23.41,34.26) 22.47,35.2 22.04,35.2 22.04,35.52 21.76,35.52 21.76,34.89 21.49,34.89 21.49,35.2 20.96,35.2 19.36,36.8 19.36,41.53 20.42,42.6 30.01,42.6 v1(31.92,40.69) 32.37,40.23 34.77,40.23 35.87,41.33 39.76,41.33 v1(40.43,40.66) v1(40.43,30.63) 39.69,29.9 34.93,29.9 33.75,31.07 32.36,31.07 v1(31.94,30.66)
  SIGNAL_2 w0.146: v1(31.94,30.66) 31.94,29.25 33.17,28.02 35.75,28.02 v1(37.59,26.18)
DDR3_A3: length 94
  TOP w0.209: U5.M18 v1(22.41,34.26) ; U10.H5 v1(32.69,30.66) ; U7.H5 v1(32.67,40.69) ; J1.7 v1(17.12,9.49) ; RN1.5 v1(38.39,26.18) ; U8.H5 v1(41.18,40.66) ; U9.H5 v1(41.18,30.63)
  SIGNAL_1 w0.146: v1(32.69,30.66) 33.73,29.62 40.16,29.62 v1(41.18,30.63) v1(41.18,40.66) 40.21,41.63 35.74,41.63 34.8,40.69 v1(32.67,40.69) 30.45,42.9 20.17,42.9 19.03,41.76 19.03,36.14 20.91,34.26 v1(22.41,34.26) 22.41,14.78 v1(17.12,9.49)
  SIGNAL_2 w0.146: v1(32.69,30.66) 32.69,29.64 33.78,28.55 36.02,28.55 v1(38.39,26.18)
DDR3_DM0: length 15.2
  TOP w0.209: U10.A4 v1(31.94,36.66) ; U5.F19 v1(23.33,41.19)
  SIGNAL_2 w0.127: v1(31.94,36.66) 30.02,38.58 29.81,38.36 29.63,38.54 30.05,38.97 29.87,39.15 29.45,38.72 29.27,38.9 29.69,39.33 29.51,39.51 29.09,39.08 28.91,39.26 29.33,39.69 29.16,39.87 28.94,39.66 27.41,41.19 v1(23.33,41.19)
DDR3_DQ0: length 15.8
  TOP w0.209: U10.C2 v1(29.7,34.41) ; U5.J17 v1(21.33,38.19)
  SIGNAL_2 w0.127: v1(21.33,38.19) 21.93,37.59 25,37.59 25.87,36.72 25.65,36.49 25.83,36.31 26.28,36.76 26.46,36.58 26,36.13 26.18,35.95 26.64,36.4 26.81,36.22 26.36,35.77 26.54,35.59 26.99,36.04 27.17,35.86 26.72,35.41 26.9,35.23 27.13,35.46 28.58,34.01 29.29,34.01 v1(29.7,34.41)
DDR3_DQ1: length 15.5
  TOP w0.209: U10.A5 v1(32.69,36.66) ; U5.F18 v1(22.33,41.19)
  SIGNAL_2 w0.127: v1(22.33,41.19) 22.75,41.61 27.74,41.61 31,38.35 31.21,38.56 31.39,38.39 30.96,37.96 31.14,37.78 31.57,38.21 31.75,38.03 31.53,37.81 v1(32.69,36.66)
DDR3_DQ2: length 13.3
  TOP w0.209: U10.C1 v1(28.95,34.41) ; U5.J18 v1(22.33,38.19)
  SIGNAL_2 w0.127: v1(28.95,34.41) 27,36.36 27.48,36.84 27.3,37.02 26.82,36.54 26.64,36.72 27.12,37.19 26.94,37.37 26.46,36.9 26.28,37.08 26.76,37.55 26.58,37.73 26.1,37.26 25.18,38.19 v1(22.33,38.19)
DDR3_DQ3: length 15.5
  TOP w0.209: U5.F17 v1(21.33,41.19) ; U10.A6 v1(33.44,36.66)
  SIGNAL_2 w0.127: v1(33.44,36.66) 33.03,36.25 31.55,36.25 27.02,40.78 22.16,40.78 22.15,40.79 21.73,40.79 v1(21.33,41.19)
DDR3_DQS0_N: length 14.4
  TOP w0.209: U5.G17 v1(21.33,40.19) ; U10.B1 v1(28.95,35.16)
  SIGNAL_2 w0.152: v1(21.33,40.19) 21.68,39.84 21.68,39.26 22.05,38.89 23.54,38.89 23.54,39.32 23.82,39.32 23.82,38.46 24.71,38.46 24.71,38.89 27.47,38.89 29.17,37.19 29.17,35.38 v1(28.95,35.16)
DDR3_DQS0_P: length 14.4
  TOP w0.209: U10.B2 v1(29.7,35.16) ; U5.G18 v1(22.33,40.19)
  SIGNAL_2 w0.152: v1(22.33,40.19) 21.99,39.84 21.99,39.38 22.18,39.19 23.24,39.19 23.24,39.62 24.13,39.62 24.13,38.76 24.41,38.76 24.41,39.19 27.6,39.19 29.48,37.32 29.48,35.38 v1(29.7,35.16)
DP_N: length 26.4
  TOP w0.152: U5.D15 v1(18.41,43.26) ; U18.19 26.2,54.69 27.12,54.69 27.26,54.55 v1(27.61,54.55)
  SIGNAL_1 w0.152: v1(27.61,54.55) 27.96,54.55 28.1,54.69 29.57,54.69 29.97,54.28 29.97,50.83 29.03,49.89 20.55,49.89 18.76,48.09 18.76,46.43 18.56,46.23 18.56,46.03 18.76,45.83 18.76,45.54 18.56,45.34 18.56,45.14 18.76,44.94 18.76,44.65 18.56,44.45 18.56,44.25 18.76,44.05 18.76,43.61 v1(18.41,43.26)
DP_P: length 26.4
  TOP w0.152: U18.20 26.17,54.99 27.12,54.99 27.26,55.13 v1(27.61,55.13) ; U5.D16 v1(19.41,43.26)
  SIGNAL_1 w0.152: v1(19.41,43.26) 19.06,43.61 19.06,47.97 20.68,49.58 29.16,49.58 30.28,50.7 30.28,54.41 29.69,54.99 28.1,54.99 27.96,55.13 v1(27.61,55.13)
LENGTH1: length 22.1
  TOP w0.127: U1.2 12.53,76.74 13.92,78.13 16.71,78.13 17.15,77.7 17.15,77.21 17.62,76.74 U2.2 19.62,76.74 19.63,76.73 21.26,76.73 22.46,77.93 25.43,77.93 26,77.36 v1(26,74.61)
  BOTTOM w0.127: U20.24 v1(26,74.61)
LENGTH2: length 22.3
  TOP w0.127: U1.4 12.42,75.44 13.04,76.05 13.14,76.05 13.15,76.04 13.26,76.04 13.33,76.12 13.33,76.22 13.21,76.35 13.21,76.45 13.28,76.53 13.39,76.53 13.51,76.4 13.62,76.4 13.69,76.48 13.69,76.58 13.68,76.59 13.68,76.7 14.84,77.85 16.49,77.85 16.79,77.55 16.79,76.26 17.62,75.44 U2.4 20.32,75.44 22.89,72.87 25.58,72.87 26,73.29 v1(26,73.81)
  BOTTOM w0.127: U20.23 v1(26,73.81)
LENGTH3: length 22.1
  TOP w0.127: U1.6 11.41,74.14 11.48,74.21 11.48,74.37 11.56,74.45 11.66,74.45 11.74,74.37 11.74,73.9 11.81,73.83 11.92,73.83 11.99,73.9 11.99,74.37 12.06,74.45 12.17,74.45 12.24,74.37 12.24,73.9 12.32,73.83 12.42,73.83 12.5,73.9 12.5,74.37 12.57,74.45 12.68,74.45 12.75,74.37 12.75,73.9 12.83,73.83 12.93,73.83 13.01,73.9 13.01,74.06 13.08,74.14 13.11,74.14 14.35,72.9 16.38,72.9 17.62,74.14 U2.6 20.53,74.14 22.46,72.21 v1(26,72.21)
  BOTTOM w0.127: U20.21 v1(26,72.21)
LENGTH4: length 22.1
  TOP w0.127: U1.7 12.67,73.49 13.9,72.26 16.46,72.26 16.46,72.33 17.62,73.49 U2.7 19.99,73.49 20.6,72.87 20.6,72.77 20.31,72.48 20.31,72.37 20.39,72.3 20.49,72.3 21.17,72.98 21.28,72.98 21.35,72.91 21.35,72.8 20.67,72.12 20.67,72.01 20.75,71.94 20.85,71.94 21.14,72.23 21.25,72.23 22.07,71.41 v1(26,71.41)
  BOTTOM w0.127: U20.20 v1(26,71.41)
PHASE_N: length 55.7
  TOP w0.2: U12.3 28.43,60.77 28.3,60.89 27.63,60.89 26.84,60.1 26.27,60.1 v1(26.01,59.85)
  TOP w0.203: U5.D12 v1(16.41,43.26)
  SIGNAL_2 w0.15: v1(26.01,59.85) 25.7,60.15 12.21,60.15 12.01,59.95 11.81,59.95 11.61,60.15 10.89,60.15 10.69,59.95 10.49,59.95 10.29,60.15 9.72,60.15 9.52,59.95 9.32,59.95 9.12,60.15 8.86,60.15 7.87,59.16 7.87,57.98 8.07,57.78 8.07,57.58 7.87,57.38 7.87,56.69 8.07,56.49 8.07,56.29 7.87,56.09 7.87,55.8 8.69,54.99 19.15,54.99 21.49,52.65 21.49,50.57 19.79,48.87 17.38,48.87 16.07,47.57 16.07,43.6 v1(16.41,43.26)
PHASE_P: length 55.9
  TOP w0.2: U12.2 28.43,61.42 28.3,61.29 27.46,61.29 26.67,60.5 26.27,60.5 v1(26.01,60.76)
  TOP w0.203: U5.D11 v1(15.41,43.26)
  SIGNAL_2 w0.15: v1(26.01,60.76) 25.7,60.45 8.74,60.45 7.57,59.28 7.57,55.68 8.56,54.69 9.53,54.69 9.73,54.49 9.93,54.49 10.13,54.69 11.36,54.69 11.56,54.49 11.76,54.49 11.96,54.69 17.23,54.69 17.43,54.49 17.63,54.49 17.83,54.69 19.03,54.69 21.19,52.52 21.19,50.7 19.66,49.17 17.25,49.17 15.77,47.69 15.77,43.63 v1(15.41,43.26)

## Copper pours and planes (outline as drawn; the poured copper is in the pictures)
Net_297 on TOP (solid shape): 38.71,54.66 31.7,54.66 31.7,61.67 38.71,61.67

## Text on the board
User.Comments: stacking allowed in region | stacked uvia to core via drc | snap stack in region | (layer based region rules) | via in pad offset - use negative value | thru hole in pad violation | create fanout | via in pad violation | core to uvia same net drc | core to core net2net drc | microvia to microvia net2net drc | microvia to core via - same net = 5 | microvia tangency - same net uvia-uvia = 0 | snap mtg hole to crosshair | layer set 6-7 assigned to ADDR Bus (blue rats) | Align these Caps | stacking violation
